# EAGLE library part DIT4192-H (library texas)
192kHz Digital Audio Transmitter Hardware Mode Source: http://focus.ti.com/lit/ds/symlink/dit4192.pdf
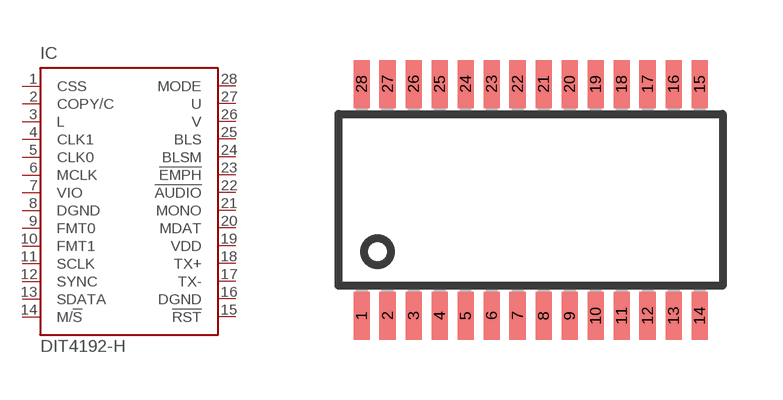
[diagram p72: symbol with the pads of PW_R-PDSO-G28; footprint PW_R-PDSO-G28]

Designator prefix IC

## DIT4192-H (MF: TEXAS INSTRUMENTS; MPN: DIT4192IPW; OC_FARNELL: 7455057; OC_NEWARK: 74C9511)  [PW_R-PDSO-G28]
1  CSS  in
2  COPY/C  in
3  L  in
4  CLK1  in
5  CLK0  in
6  MCLK  in
7  VIO  pwr
8  DGND  pwr
9  FMT0  in
10  FMT1  in
11  SCLK
12  SYNC
13  SDATA  in
14  M/!S  in
15  !RST  in
16  DGND  pwr
17  TX-  out
18  TX+  out
19  VDD  pwr
20  MDAT  in
21  MONO  in
22  !AUDIO  in
23  !EMPH  in
24  BLSM  in
25  BLS
26  V  in
27  U  in
28  MODE  in

## Footprint PW_R-PDSO-G28 (pad centres in mm)
PLASTIC SMALL-OUTLINE PACKAGE SO 28 JEDEC MO-153, PW Type Source: www.ti.com/.. slvs087l.pdf
smd 0.4 x 1.2: 1 -4.225,-2.9; 2 -3.575,-2.9; 3 -2.925,-2.9; 4 -2.275,-2.9; 5 -1.625,-2.9; 6 -0.975,-2.9; 7 -0.325,-2.9; 8 0.325,-2.9; 9 0.975,-2.9; 10 1.625,-2.9; 11 2.275,-2.9; 12 2.925,-2.9; 13 3.575,-2.9; 14 4.225,-2.9; 15 4.225,2.9; 16 3.575,2.9; 17 2.925,2.9; 18 2.275,2.9; 19 1.625,2.9; 20 0.975,2.9; 21 0.325,2.9; 22 -0.325,2.9; 23 -0.975,2.9; 24 -1.625,2.9; 25 -2.275,2.9; 26 -2.925,2.9; 27 -3.575,2.9; 28 -4.225,2.9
